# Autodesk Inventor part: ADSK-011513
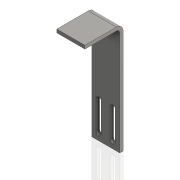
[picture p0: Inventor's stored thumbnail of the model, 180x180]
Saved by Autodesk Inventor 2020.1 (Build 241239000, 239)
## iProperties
Created: 1999-12
Part Number: ADSK-011513
Material: 1.0312 DC05
Document SubType Name: Tôlerie
Designer: sspink
Density: 1 g/cm^3
Sheet Metal Rule: Stahlblech 1.0312 - DC05 -   6.0 mm
Appearance: Stahl
Mass: 70.2913 g
Surface Area: 286.506 cm^2
Volume: 70.2913 cm^3
Flat Pattern Width: 25.4572 cm
Flat Pattern Length: 5 cm
Flat Pattern Area: 127.286 cm^2
Sheet Metal Width: 254,572 mm
Sheet Metal Length: 50,000 mm
Sheet Metal Area: 12728,584 mm^2
Control State: 0
Master: False
Checked Out: False
Shininess: 60.0
Length Units: 11269
Angle Units: 11279
Time Units: 11290
Mass Units: 11283
Length Display Precision: 3
Angle Display Precision: 2
Compacted: True
Cutlength: 10
Material Desc: FLAT,HRS,0.250 X 2.00
Material_number: A084333
G_L: 50x254,6 mm
Thickness: 6,000 mm
Dimensions: 50x197x68 mm
Mass: 0,07 kg
Semi finished: Stahlblech 1.0312 - DC05 -   6.0 mm
DocNumber: ADSK-011513.ipt
Folder: 01 - Themengebiete\Simplification\01 - Packaging machine\
VDS_Category: 3D Komponenten
Density: 0.0
Volumn: 0.0
Area: 0.0
PropertySet Name: Model Information
Author: sspink
Revision Number: -
Title: angle
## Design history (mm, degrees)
node "Solide1"
  node "Extrusion1" dims "d2" = 6 (= Thickness), "d3" = 0
  node "Extrusion2" dims "d10" = 25.4, "d11" = 0
  node "Extrusion3" dims "d14" = 50.8, "d15" = 0
  node "Bend1" dims "d18" = 6 (= BendRadius), "d19" = 6 (= BendReliefWidth), "d20" = 3 (= BendReliefDepth), "d21" = 12 (= MinimumRemnant), "d22" = 6 (derived), "SeamGap" = 0.00508, "MinimumRemnant" = 12 (derived), "BendReliefWidth" = 6 (derived)
sketch "Sketch1"
  geometry: L1 (25, 98.5)-(-25, 98.5); L2 (-25, 98.5)-(-25, -98.5); L3 (-25, -98.5)-(25, -98.5); L4 (25, -98.5)-(25, 98.5); 3 further points
  constraints: 8 end point, 2 midpoint, 2 parallel, 1 horizontal, 1 horizontal alignment, 1 perpendicular, 1 vertical alignment
  dimensions: "d0" = 50 distance of L2.end L3.end; "d1" = 197 distance of L1.end L2.end
sketch "Sketch2"
  geometry: L1 (-17, -86)-(-8, -86); L2 (-8, -86)-(-8, -35.2); L3 (-8, -35.2)-(-17, -35.2); L4 (-17, -35.2)-(-17, -86); L5 (8, -86)-(17, -86); L6 (17, -86)-(17, -35.2); L7 (17, -35.2)-(8, -35.2); L8 (8, -35.2)-(8, -86); L9 (0, -98.5)-(0, 98.5); L10 (25, -98.5)-(-25, -98.5) reference; L11 (-25, 98.5)-(25, 98.5) reference; L12 (12.5, -86)-(12.5, -35.2); L13 (-12.5, -86)-(-12.5, -35.2); L14 (12.5, -60.6)-(-12.5, -60.6); A1 r 4.5 centre (-12.5, -35.2) between (-8, -35.2) and (-17, -35.2); A2 r 4.5 centre (-12.5, -86) between (-17, -86) and (-8, -86); A3 r 4.5 centre (12.5, -35.2) between (17, -35.2) and (8, -35.2); A4 r 4.5 centre (12.5, -86) between (8, -86) and (17, -86); 1 further point
  constraints: 24 end point, 8 point on circle, 4 centre point, 4 midpoint, 4 parallel, 4 tangent, 2 equal length, 2 horizontal, 2 perpendicular, 2 vertical, 1 collinear, 1 point on line
  dimensions: "d5" = 50.8 distance between parallel lines of L1 L3; "d23" = 12.5 distance between parallel lines of L10 L1; "d24" = 9 distance between parallel lines of L2 L4; "d26" = 25 distance of L14.start L14.end
workplane "Arbeitsebene1"
workplane "Arbeitsebene2"
sketch "Sketch3"
  geometry: L1 (6, 197)-(68, 197); L2 (68, 197)-(68, 191); L3 (68, 191)-(6, 191); L4 (6, 191)-(6, 197)
  constraints: 8 end point, 2 parallel, 1 horizontal, 1 perpendicular
  dimensions: "d12" = 6 distance of L1.end L2.end (= Thickness); "d13" = 62 distance of L2.end L3.end
node "FlatPattern"
node "Corps solides"
node "Corps surfaciques"
feature "Extrusion_mise_à_plat2" dims "d0" = 6 (derived)
other parameters: "Thickness" = 6 (derived), "BendRadius" = 6 (derived), "BendReliefDepth" = 3 (derived), "CornerReliefSize" = 24 (derived), "TransitionRadius" = 6 (derived), "TailleRayonJacobi" = 6 (derived), "TailleJeu" = 6 (derived)
